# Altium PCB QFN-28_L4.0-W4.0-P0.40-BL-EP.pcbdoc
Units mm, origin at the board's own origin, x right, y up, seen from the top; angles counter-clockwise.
Board outline 17.18 x 17.55 mm, 2 copper layers (Top Layer, Bottom Layer), stack 0 mm thick; 1 components, 0 nets, 29 pads, 0 vias.
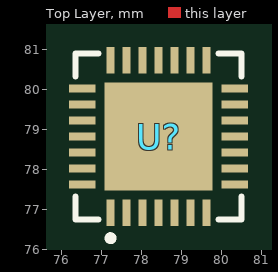
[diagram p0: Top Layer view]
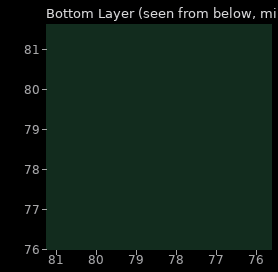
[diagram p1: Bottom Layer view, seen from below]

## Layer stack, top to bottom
Top Layer: signal copper (thickness not stored)
Bottom Layer: signal copper (thickness not stored)

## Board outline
87.03,69.85 69.85,69.85 69.85,87.405 87.03,87.405

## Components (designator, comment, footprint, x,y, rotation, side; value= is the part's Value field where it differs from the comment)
U? "" QFN-28_L4.0-W4.0-P0.40-BL-EP 78.44,78.815 r0 top

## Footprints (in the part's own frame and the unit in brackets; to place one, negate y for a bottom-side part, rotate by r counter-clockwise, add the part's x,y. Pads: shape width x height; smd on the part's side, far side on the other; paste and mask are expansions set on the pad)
QFN-28_L4.0-W4.0-P0.40-BL-EP [mm]
  rect 0.2x0.665 smd paste-100 mask+0.051: 1(-1.2,-1.908) 2(-0.8,-1.908) 3(-0.4,-1.908) 4(0,-1.908) 5(0.4,-1.908) 6(0.8,-1.908) 7(1.2,-1.908) 15(1.2,1.908) 16(0.8,1.908) 17(0.4,1.908) 18(0,1.908) 19(-0.4,1.908) 20(-0.8,1.908) 21(-1.2,1.908)
  rect 0.665x0.2 smd paste-100 mask+0.051: 8(1.908,-1.2) 9(1.908,-0.8) 10(1.908,-0.4) 11(1.908,0) 12(1.908,0.4) 13(1.908,0.8) 14(1.908,1.2) 22(-1.908,1.2) 23(-1.908,0.8) 24(-1.908,0.4) 25(-1.908,0) 26(-1.908,-0.4) 27(-1.908,-0.8) 28(-1.908,-1.2)
  rect 2.7x2.7 smd paste-100 mask+0.051: 29(0,0)
  silkscreen extent -2.08,-2.61 2.08,2.08

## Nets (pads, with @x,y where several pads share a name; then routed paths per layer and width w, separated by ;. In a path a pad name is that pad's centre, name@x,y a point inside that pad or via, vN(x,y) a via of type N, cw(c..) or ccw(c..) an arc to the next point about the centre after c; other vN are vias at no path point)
pads on no net: U?.1 U?.2 U?.3 U?.4 U?.5 U?.6 U?.7 U?.8 U?.9 U?.10 U?.11 U?.12 U?.13 U?.14 U?.15 U?.16 U?.17 U?.18 U?.19 U?.20 U?.21 U?.22 U?.23 U?.24 U?.25 U?.26 U?.27 U?.28 U?.29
